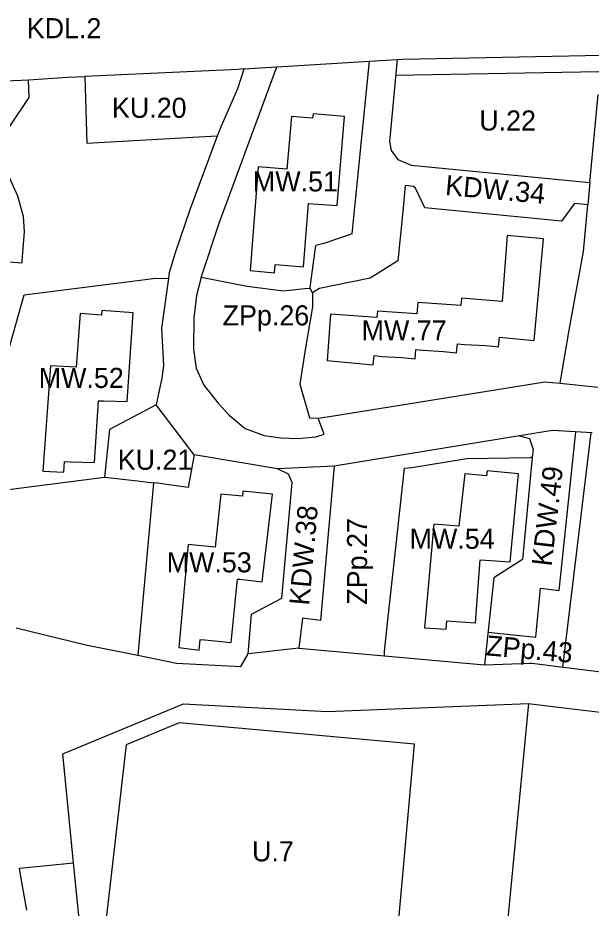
# Model space of a CAD drawing. Extents: x 7424434 to 7425898, y 5541432 to 5542659.
# Drawn here: x 7425250.1 to 7425392.8, y 5541625.5 to 5541847 of the extents above; entities that cross this region are included whole.
import ezdxf

# ---------------------------------------------------------------- set-up
doc = ezdxf.new("R2010")
doc.units = 0
for name, color, linetype in [('linie rozgraniczające', 7, 'Continuous'), ('nieprzekraczalne linie zabudowy', 7, 'Continuous'), ('obowiazujace linie zabudowy', 7, 'Continuous'), ('przeznaczenia terenów', 7, 'Continuous')]:
    doc.layers.add(name, color=color, linetype=linetype)

msp = doc.modelspace()

# ---------------------------------------------------------------- linework, layer by layer
at = {"layer": 'linie rozgraniczające'}
for p, q in [((7425345.98, 5541836.72), (7425395.46, 5541837.71)), ((7425300.19, 5541795.97), (7425314.6, 5541834.8)), ((7425306.42, 5541834.3), (7425314.6, 5541834.8)), ((7425314.6, 5541834.8), (7425337.62, 5541836.25)), ((7425333.97, 5541799.96), (7425337.62, 5541836.25)), ((7425337.62, 5541836.25), (7425344.52, 5541836.64)), ((7425344.52, 5541836.64), (7425342.61, 5541816.28)), ((7425344.52, 5541836.64), (7425345.98, 5541836.72)), ((7425304.92, 5541834.21), (7425266.79, 5541832.42)), ((7425304.89, 5541829.42), (7425306.42, 5541834.3)), ((7425306.42, 5541834.3), (7425304.92, 5541834.21)), ((7425300.78, 5541820.15), (7425304.89, 5541829.42)), ((7425392.52, 5541806.05), (7425394.55, 5541827.93)), ((7425299.85, 5541817.67), (7425300.78, 5541820.15)), ((7425267.3, 5541815.85), (7425295.14, 5541817.41)), ((7425293.09, 5541799.57), (7425299.85, 5541817.67)), ((7425295.14, 5541817.41), (7425299.85, 5541817.67)), ((7425342.61, 5541816.28), (7425343.02, 5541813.98)), ((7425343.02, 5541813.98), (7425344.66, 5541811.76)), ((7425344.66, 5541811.76), (7425348, 5541810.41)), ((7425348, 5541810.41), (7425392.52, 5541806.05)), ((7425392.52, 5541806.05), (7425392, 5541800.49)), ((7425346.5, 5541805.33), (7425345.92, 5541798.82)), ((7425348.63, 5541805.1), (7425346.5, 5541805.33)), ((7425349.14, 5541804.67), (7425348.63, 5541805.1)), ((7425351.46, 5541799.78), (7425349.14, 5541804.67)), ((7425289.28, 5541788.4), (7425293.09, 5541799.57)), ((7425333.3, 5541793.25), (7425333.97, 5541799.96)), ((7425385.42, 5541796.41), (7425351.46, 5541799.78)), ((7425388.64, 5541800.84), (7425385.42, 5541796.41)), ((7425392, 5541800.49), (7425388.64, 5541800.84)), ((7425390.92, 5541788.93), (7425392, 5541800.49)), ((7425345.92, 5541798.82), (7425344.72, 5541786.6)), ((7425295.71, 5541782.44), (7425300.19, 5541795.97)), ((7425333.3, 5541793.25), (7425326.26, 5541790.84)), ((7425326.26, 5541790.84), (7425324.28, 5541790.36)), ((7425287.88, 5541783.68), (7425289.28, 5541788.4)), ((7425322.98, 5541780.59), (7425324.28, 5541790.36)), ((7425387.35, 5541769.28), (7425390.92, 5541788.93)), ((7425251.17, 5541786.09), (7425251.18, 5541786.11)), ((7425251.18, 5541786.11), (7425251.22, 5541786.51)), ((7425344.72, 5541786.6), (7425337.85, 5541782.28)), ((7425251.69, 5541778.11), (7425284.5, 5541782.29)), ((7425284.5, 5541782.29), (7425287.61, 5541782.2)), ((7425285.94, 5541769.85), (7425287.67, 5541782.2)), ((7425287.61, 5541782.2), (7425287.67, 5541782.2)), ((7425287.67, 5541782.2), (7425287.88, 5541783.67)), ((7425287.88, 5541783.67), (7425287.88, 5541783.68)), ((7425295.71, 5541782.44), (7425294.59, 5541777.92)), ((7425307.23, 5541780.22), (7425295.71, 5541782.44)), ((7425337.85, 5541782.28), (7425325.23, 5541779.7)), ((7425316.21, 5541779.02), (7425307.23, 5541780.22)), ((7425321.54, 5541779.62), (7425316.21, 5541779.02)), ((7425322.85, 5541779.65), (7425321.54, 5541779.62)), ((7425322.85, 5541779.65), (7425322.98, 5541780.59)), ((7425323.46, 5541778.59), (7425322.85, 5541779.65)), ((7425325.23, 5541779.7), (7425323.46, 5541778.59)), ((7425245.41, 5541755.97), (7425251.69, 5541778.11)), ((7425294.59, 5541777.92), (7425293.9, 5541772.4)), ((7425323.46, 5541778.59), (7425323.45, 5541775.14)), ((7425323.45, 5541775.14), (7425321.52, 5541763.96)), ((7425293.9, 5541772.4), (7425293.82, 5541764.62)), ((7425286.47, 5541760.48), (7425285.94, 5541769.85)), ((7425385.47, 5541758.14), (7425387.35, 5541769.28)), ((7425293.82, 5541764.62), (7425294.47, 5541759.88)), ((7425321.52, 5541763.96), (7425320.34, 5541755.92)), ((7425286.03, 5541757.39), (7425286.47, 5541760.48)), ((7425294.47, 5541759.88), (7425296.4, 5541755.6)), ((7425284.6, 5541750.86), (7425286.03, 5541757.39)), ((7425385.12, 5541756.09), (7425385.47, 5541758.14)), ((7425296.4, 5541755.6), (7425300.01, 5541751.16)), ((7425320.34, 5541755.92), (7425322.73, 5541747.54)), ((7425328.21, 5541747.92), (7425381.31, 5541756.47)), ((7425381.31, 5541756.47), (7425385.12, 5541756.09)), ((7425385.12, 5541756.09), (7425394.51, 5541755.17)), ((7425284.58, 5541750.77), (7425272.91, 5541744.59)), ((7425284.58, 5541750.77), (7425284.6, 5541750.86)), ((7425293.99, 5541738.27), (7425284.58, 5541750.77)), ((7425300.01, 5541751.16), (7425302.69, 5541748.13)), ((7425302.69, 5541748.13), (7425306.67, 5541744.84)), ((7425322.73, 5541747.54), (7425324.88, 5541747.44)), ((7425324.88, 5541747.44), (7425328.21, 5541747.92)), ((7425326.36, 5541743.44), (7425324.88, 5541747.44)), ((7425272.91, 5541744.59), (7425271.72, 5541732.74)), ((7425306.67, 5541744.84), (7425311.45, 5541743.08)), ((7425383.22, 5541744.34), (7425375.01, 5541743.01)), ((7425393.08, 5541743.75), (7425383.22, 5541744.34)), ((7425384.88, 5541704.52), (7425389.03, 5541743.99)), ((7425311.45, 5541743.08), (7425315.57, 5541742.52)), ((7425315.57, 5541742.52), (7425319.81, 5541742.39)), ((7425319.81, 5541742.39), (7425324.28, 5541742.79)), ((7425324.28, 5541742.79), (7425326.36, 5541743.44)), ((7425375.01, 5541743.01), (7425328.83, 5541735.5)), ((7425375.01, 5541743.01), (7425377.47, 5541742.32)), ((7425377.47, 5541742.32), (7425378.35, 5541739.6)), ((7425385.77, 5541685.49), (7425392.79, 5541743.77)), ((7425378.35, 5541739.6), (7425378.16, 5541737.6)), ((7425293.99, 5541738.27), (7425292.47, 5541730.17)), ((7425314.73, 5541734.79), (7425293.99, 5541738.27)), ((7425348.21, 5541735.13), (7425361.87, 5541737.42)), ((7425361.87, 5541737.42), (7425377.75, 5541737.6)), ((7425378.16, 5541737.6), (7425375.71, 5541712.27)), ((7425378.16, 5541737.6), (7425377.75, 5541737.6)), ((7425328.83, 5541735.5), (7425314.73, 5541734.79)), ((7425328.83, 5541735.5), (7425325.46, 5541697.06)), ((7425346.37, 5541735), (7425348.21, 5541735.13)), ((7425317.48, 5541733.5), (7425314.73, 5541734.79)), ((7425318.42, 5541731.43), (7425317.48, 5541733.5)), ((7425343.59, 5541709.94), (7425346.37, 5541735)), ((7425247.77, 5541729.63), (7425271.72, 5541732.74)), ((7425271.72, 5541732.74), (7425271.75, 5541732.74)), ((7425271.75, 5541732.74), (7425279.89, 5541731.81)), ((7425279.89, 5541731.81), (7425283.9, 5541731.36)), ((7425283.9, 5541731.36), (7425283.31, 5541724.92)), ((7425284, 5541731.35), (7425283.9, 5541731.36)), ((7425284.93, 5541731.24), (7425284, 5541731.35)), ((7425287.13, 5541730.93), (7425284.93, 5541731.24)), ((7425292.47, 5541730.17), (7425287.13, 5541730.93)), ((7425315.85, 5541702.65), (7425318.42, 5541731.43)), ((7425283.31, 5541724.92), (7425279.99, 5541688.44)), ((7425375.71, 5541712.27), (7425368.61, 5541707.69)), ((7425342.26, 5541697.97), (7425343.59, 5541709.94)), ((7425368.61, 5541707.69), (7425366.24, 5541686.02)), ((7425379.09, 5541692.96), (7425380.24, 5541705.14)), ((7425380.24, 5541705.14), (7425384.88, 5541704.52)), ((7425308.25, 5541698.65), (7425315.85, 5541702.65)), ((7425307.42, 5541688.76), (7425308.25, 5541698.65)), ((7425320.99, 5541697.65), (7425320.08, 5541690.19)), ((7425325.46, 5541697.06), (7425320.99, 5541697.65)), ((7425341.4, 5541689.36), (7425342.26, 5541697.97)), ((7425249.71, 5541695.25), (7425267.02, 5541691.03)), ((7425367.13, 5541694.15), (7425379.09, 5541692.96)), ((7425267.02, 5541691.03), (7425279.99, 5541688.42)), ((7425305.58, 5541685.61), (7425307.42, 5541688.76)), ((7425320.08, 5541690.19), (7425307.42, 5541688.76)), ((7425320.08, 5541690.19), (7425341.35, 5541688.27)), ((7425341.35, 5541688.27), (7425341.4, 5541689.36)), ((7425279.99, 5541688.44), (7425279.99, 5541688.42)), ((7425279.99, 5541688.42), (7425289.62, 5541686.48)), ((7425289.62, 5541686.48), (7425305.58, 5541685.61)), ((7425341.35, 5541688.27), (7425366.24, 5541686.02)), ((7425366.24, 5541686.02), (7425377.66, 5541686.48)), ((7425377.66, 5541686.48), (7425378.07, 5541686.43)), ((7425378.07, 5541686.43), (7425387.93, 5541685.22)), ((7425387.93, 5541685.22), (7425398.02, 5541683.98)), ((7425261.27, 5541663.94), (7425291.34, 5541676.37)), ((7425291.34, 5541676.37), (7425327.1, 5541674.42)), ((7425327.1, 5541674.42), (7425377.25, 5541676.46)), ((7425377.25, 5541676.46), (7425369.41, 5541595.18)), ((7425377.25, 5541676.46), (7425386.67, 5541675.3)), ((7425386.67, 5541675.3), (7425401.64, 5541673.46)), ((7425264, 5541636.79), (7425261.27, 5541663.94)), ((7425250.49, 5541635.43), (7425264, 5541636.79)), ((7425250.96, 5541632.84), (7425250.49, 5541635.43)), ((7425266.99, 5541607.03), (7425264, 5541636.79)), ((7425252.31, 5541625.03), (7425250.96, 5541632.84))]:
    msp.add_line(p, q, dxfattribs=at)
for points in [[(7425152.96, 5541800.98), (7425157.45, 5541800.54), (7425181.73, 5541797.75), (7425186.96, 5541792.35), (7425212.77, 5541790.02), (7425218.43, 5541789.51), (7425235.03, 5541787.34), (7425251.17, 5541786.09), (7425251.22, 5541786.51), (7425251.78, 5541793.87), (7425251.55, 5541797.6), (7425250.15, 5541802.68), (7425247.92, 5541807.48), (7425244.17, 5541812.41), (7425244.15, 5541812.44), (7425248.22, 5541820.16), (7425252.92, 5541827.21), (7425252.8, 5541831.58)], [(7425155.16, 5541827.7), (7425160.36, 5541827.63), (7425166.42, 5541827.54), (7425167.04, 5541827.57), (7425175.52, 5541827.87), (7425190.4, 5541828.41), (7425205.13, 5541828.95), (7425219.03, 5541829.71), (7425247.23, 5541831.37), (7425252.8, 5541831.58)], [(7425252.8, 5541831.58), (7425262.46, 5541832.27), (7425266.79, 5541832.42)], [(7425266.79, 5541832.42), (7425266.79, 5541832.42), (7425267.3, 5541815.85)]]:
    msp.add_lwpolyline(points, dxfattribs=at)
at = {"layer": 'nieprzekraczalne linie zabudowy'}
msp.add_line((7425394.74, 5541833.62), (7425344.16, 5541832.69), dxfattribs=at)
msp.add_lwpolyline([(7425343.14, 5541602.25), (7425348.81, 5541666.31), (7425290.29, 5541671.61), (7425277.07, 5541666.14), (7425270.65, 5541610.63)], close=True, dxfattribs=at)
at = {"layer": 'obowiazujace linie zabudowy'}
for points in [[(7425307.98, 5541784.16), (7425313.99, 5541783.58), (7425314.15, 5541785.64), (7425315.23, 5541785.56), (7425321.23, 5541785.09), (7425322.49, 5541800.82), (7425323.66, 5541800.74), (7425329.63, 5541800.33), (7425331.45, 5541822.5), (7425323.59, 5541823.11), (7425323.5, 5541822.04), (7425318.21, 5541822.45), (7425317.09, 5541809.37), (7425309.96, 5541809.92)], [(7425371.91, 5541792.87), (7425370.68, 5541776.48), (7425360.55, 5541777.24), (7425360.41, 5541775.43), (7425349.65, 5541776.24), (7425349.43, 5541773.34), (7425339.64, 5541774.08), (7425339.51, 5541772.44), (7425327.98, 5541773.31), (7425327.11, 5541761.78), (7425338.6, 5541760.67), (7425338.82, 5541762.98), (7425340.7, 5541762.8), (7425345.69, 5541762.5), (7425348.99, 5541762.19), (7425349.21, 5541764.51), (7425351.04, 5541764.33), (7425356.04, 5541764.03), (7425359.33, 5541763.71), (7425359.54, 5541765.89), (7425361.3, 5541765.73), (7425366.57, 5541765.5), (7425369.78, 5541765.2), (7425370.01, 5541767.59), (7425378.62, 5541766.76), (7425380.96, 5541792.03)], [(7425256.33, 5541734.24), (7425261.57, 5541734), (7425261.75, 5541736.61), (7425263.23, 5541736.57), (7425269.19, 5541736.42), (7425270.15, 5541751.73), (7425271.42, 5541751.7), (7425277.35, 5541751.54), (7425278.83, 5541773.59), (7425271.05, 5541774.19), (7425270.96, 5541773.03), (7425265.66, 5541773.44), (7425264.63, 5541760.15), (7425258.23, 5541760.47)], [(7425361.42, 5541733.56), (7425359.9, 5541720.57), (7425353.65, 5541721.04), (7425351.33, 5541695.29), (7425356.73, 5541694.89), (7425356.89, 5541697.03), (7425357.99, 5541696.95), (7425364.07, 5541696.5), (7425365.23, 5541712.19), (7425366.55, 5541712.09), (7425372.68, 5541711.64), (7425374.77, 5541733.57), (7425366.95, 5541734.35), (7425366.79, 5541733.11)], [(7425295.21, 5541689.71), (7425295.5, 5541692.36), (7425296.64, 5541692.25), (7425303.18, 5541691.63), (7425304.77, 5541707.39), (7425305.38, 5541707.32), (7425310.95, 5541706.68), (7425313.48, 5541728.49), (7425306.08, 5541729.22), (7425306.03, 5541728.03), (7425300.61, 5541728.51), (7425299.24, 5541715.33), (7425292.54, 5541715.98), (7425290.2, 5541690.32)]]:
    msp.add_lwpolyline(points, close=True, dxfattribs=at)

# ---------------------------------------------------------------- texts
at = {"layer": 'przeznaczenia terenów'}
for s, p in [('KDL.2', (7425252.33, 5541841.96)), ('KU.20', (7425273.54, 5541822.15)), ('U.22', (7425364.97, 5541818.99)), ('MW.51', (7425308.62, 5541803.83)), ('ZPp.26', (7425301.09, 5541770.5)), ('MW.77', (7425335.68, 5541766.76)), ('MW.52', (7425255.31, 5541754.94)), ('KU.21', (7425274.97, 5541734.58)), ('MW.54', (7425347.63, 5541714.91)), ('MW.53', (7425287.16, 5541709.06)), ('U.7', (7425308.41, 5541637.15))]:
    msp.add_text(s, height=5, dxfattribs=at).set_placement(p)
for s, rotation, p in [('KDW.34', 354.8483, (7425356.36, 5541802.97)), ('KDW.49', 83.3442, (7425382.96, 5541710.4)), ('KDW.38', 85.0178, (7425322.64, 5541700.69)), ('ZPp.27', 90, (7425337.05, 5541701)), ('ZPp.43', 354.975, (7425366.53, 5541688.42))]:
    msp.add_text(s, height=5, rotation=rotation, dxfattribs=at).set_placement(p)

doc.saveas('drawing.dxf')
